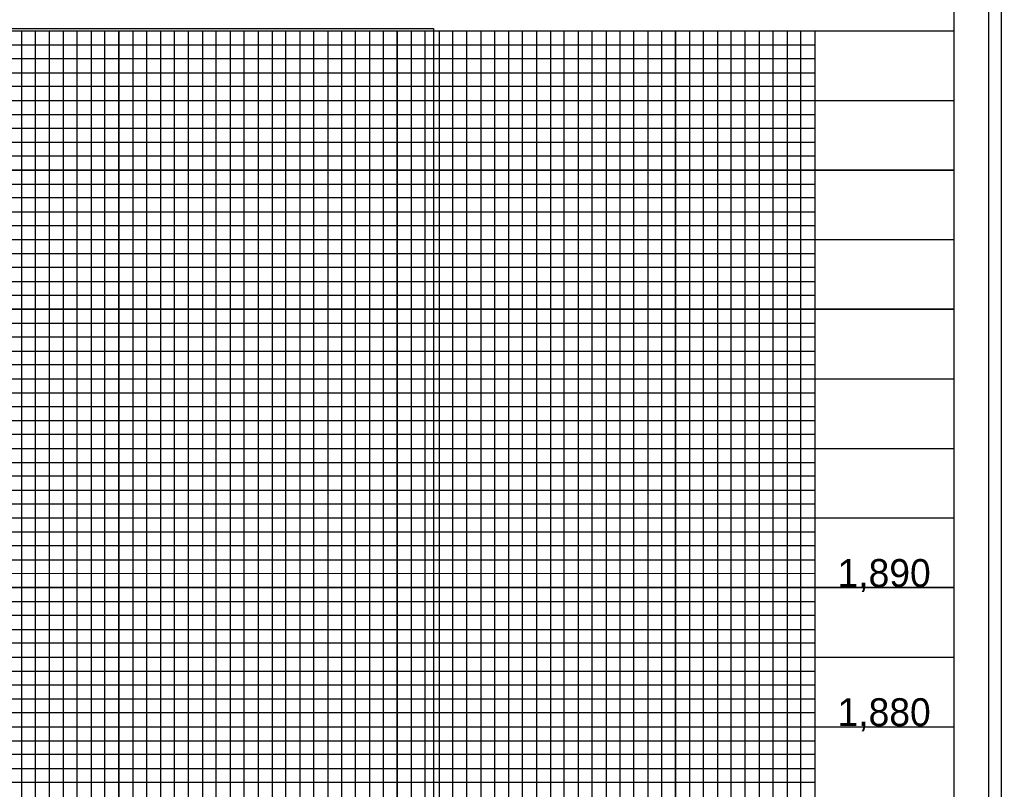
# Model space of a CAD drawing. Extents: x 557032 to 558716, y 525869 to 526969.
# Drawn here: x 558363.8 to 558716.5, y 526146.7 to 526423.3 of the extents above; entities that cross this region are included whole.
import ezdxf

# ---------------------------------------------------------------- set-up
doc = ezdxf.new("R2010")
doc.units = 0
for name, color, linetype in [('Exist Vertical Profile Vertical Axis Label', 7, 'Continuous'), ('Scratch_Level_5', 7, 'Continuous'), ('Sheet DOT Grid CELL', 7, 'Continuous'), ('Sheet Layout Profile Border Port 2', 7, 'Continuous'), ('Sheet Plot Border Inside CELL', 7, 'Continuous'), ('Sheet Plot Border Outside CELL', 7, 'Continuous'), ('Sheet Profile CELL', 7, 'Continuous'), ('Sheet Profile Grid Major CELL', 7, 'Continuous'), ('Sheet Profile Grid Middle CELL', 7, 'Continuous'), ('Sheet Profile Grid Minor CELL', 7, 'Continuous')]:
    doc.layers.add(name, color=color, linetype=linetype)

msp = doc.modelspace()

# ---------------------------------------------------------------- linework, layer by layer
at = {"layer": 'Scratch_Level_5'}
msp.add_lwpolyline([(557997.44, 526420.09), (558512.44, 526420.09), (558512.49, 525920.09), (557997.49, 525920.09)], close=True, dxfattribs=at)
at = {"layer": 'Sheet DOT Grid CELL'}
for p, q in [((557199.45, 526419.22), (558699.34, 526419.22)), ((558399.45, 526419.22), (558399.45, 525919.22)), ((558449.45, 526419.22), (558449.45, 525919.22)), ((558499.45, 526419.22), (558499.45, 525919.22)), ((558549.45, 526419.22), (558549.45, 525919.22)), ((558599.45, 526419.22), (558599.45, 525919.22)), ((558649.45, 526419.22), (558649.45, 525919.22)), ((557199.45, 526369.22), (558699.34, 526369.22)), ((557199.45, 526319.22), (558699.34, 526319.22)), ((557199.45, 526269.22), (558699.34, 526269.22)), ((557199.45, 526219.22), (558699.34, 526219.22)), ((557199.45, 526169.22), (558699.34, 526169.22))]:
    msp.add_line(p, q, dxfattribs=at)
at = {"layer": 'Sheet Layout Profile Border Port 2'}
msp.add_lwpolyline([(557249.45, 526419.22), (558649.45, 526419.22), (558649.45, 525919.22), (557249.45, 525919.22)], close=True, dxfattribs=at)
at = {"layer": 'Sheet Plot Border Inside CELL'}
msp.add_lwpolyline([(557045.45, 525891.67), (558711.95, 525891.67), (558711.95, 526946.77), (557045.45, 526946.77)], close=True, dxfattribs=at)
at = {"layer": 'Sheet Plot Border Outside CELL'}
msp.add_lwpolyline([(557032.45, 525869.22), (558716.45, 525869.22), (558716.45, 526969.22), (557032.45, 526969.22)], close=True, dxfattribs=at)
at = {"layer": 'Sheet Profile CELL'}
msp.add_line((557199.45, 526419.22), (558699.45, 526419.22), dxfattribs=at)
msp.add_lwpolyline([(558699.45, 526944.22), (557199.45, 526944.22), (557199.45, 525894.22), (558699.45, 525894.22)], close=True, dxfattribs=at)
at = {"layer": 'Sheet Profile Grid Major CELL'}
for p, q in [((558399.45, 526419.22), (558449.45, 526419.22)), ((558499.45, 526419.22), (558549.45, 526419.22)), ((558599.45, 526419.22), (558649.45, 526419.22))]:
    msp.add_line(p, q, dxfattribs=at)
for points in [[(558349.45, 525919.22), (558399.45, 525919.22), (558399.45, 526419.22), (558449.45, 526419.22), (558449.45, 525919.22), (558499.45, 525919.22), (558499.45, 526419.22), (558549.45, 526419.22), (558549.45, 526047.76)], [(558599.45, 526047.76), (558599.45, 526419.22), (558649.45, 526419.22), (558649.45, 525919.22)], [(558699.45, 526369.22), (557199.45, 526369.22)], [(558699.45, 526319.22), (557199.45, 526319.22), (557199.45, 526269.22), (558699.45, 526269.22)], [(558699.45, 526219.22), (557199.45, 526219.22), (557199.45, 526169.22), (558699.45, 526169.22)]]:
    msp.add_lwpolyline(points, dxfattribs=at)
at = {"layer": 'Sheet Profile Grid Middle CELL'}
for points in [[(558324.45, 526419.22), (558374.45, 526419.22), (558374.45, 525919.22), (558424.45, 525919.22), (558424.45, 526419.22), (558474.45, 526419.22), (558474.45, 525919.22), (558524.45, 525919.22), (558524.45, 526419.22), (558574.45, 526419.22), (558574.45, 526047.76)], [(558624.45, 526047.76), (558624.45, 526419.22)], [(557199.45, 526394.22), (558699.45, 526394.22)], [(558699.45, 526344.22), (557199.45, 526344.22), (557199.45, 526294.22), (558699.45, 526294.22)], [(558699.45, 526244.22), (557199.45, 526244.22), (557199.45, 526194.22), (558699.45, 526194.22)]]:
    msp.add_lwpolyline(points, dxfattribs=at)
at = {"layer": 'Sheet Profile Grid Minor CELL'}
for p, q in [((557249.45, 526414.22), (558649.45, 526414.22)), ((558649.45, 526409.22), (557249.45, 526409.22)), ((557249.45, 526404.22), (558649.45, 526404.22)), ((558649.45, 526399.22), (557249.45, 526399.22)), ((557249.45, 526389.22), (558649.45, 526389.22)), ((558649.45, 526384.22), (557249.45, 526384.22)), ((557249.45, 526379.22), (558649.45, 526379.22)), ((558649.45, 526374.22), (557249.45, 526374.22)), ((557249.45, 526364.22), (558649.45, 526364.22)), ((558649.45, 526359.22), (557249.45, 526359.22)), ((557249.45, 526354.22), (558649.45, 526354.22)), ((558649.45, 526349.22), (557249.45, 526349.22)), ((557249.45, 526339.22), (558649.45, 526339.22)), ((558649.45, 526334.22), (557249.45, 526334.22)), ((557249.45, 526329.22), (558649.45, 526329.22)), ((558649.45, 526324.22), (557249.45, 526324.22)), ((557249.45, 526314.22), (558649.45, 526314.22)), ((558649.45, 526309.22), (557249.45, 526309.22)), ((557249.45, 526304.22), (558649.45, 526304.22)), ((558649.45, 526299.22), (557249.45, 526299.22)), ((557249.45, 526289.22), (558649.45, 526289.22)), ((558649.45, 526284.22), (557249.45, 526284.22)), ((557249.45, 526279.22), (558649.45, 526279.22)), ((558649.45, 526274.22), (557249.45, 526274.22)), ((557249.45, 526264.22), (558649.45, 526264.22)), ((558649.45, 526259.22), (557249.45, 526259.22)), ((557249.45, 526254.22), (558649.45, 526254.22)), ((558649.45, 526249.22), (557249.45, 526249.22)), ((557249.45, 526239.22), (558649.45, 526239.22)), ((558649.45, 526234.22), (557249.45, 526234.22)), ((557249.45, 526229.22), (558649.45, 526229.22)), ((558649.45, 526224.22), (557249.45, 526224.37)), ((557249.45, 526214.22), (558649.45, 526214.22)), ((558649.45, 526209.22), (557249.45, 526209.22)), ((557249.45, 526204.22), (558649.45, 526204.22)), ((558649.45, 526199.22), (557249.45, 526199.22)), ((557249.45, 526189.22), (558649.45, 526189.22)), ((558649.45, 526184.22), (557249.45, 526184.22)), ((557249.45, 526179.22), (558649.45, 526179.22)), ((558649.45, 526174.22), (557249.45, 526174.22)), ((557249.45, 526164.22), (558649.45, 526164.22)), ((558649.45, 526159.22), (557249.45, 526159.22)), ((557249.45, 526154.22), (558649.45, 526154.22)), ((558649.45, 526149.22), (557249.45, 526149.22))]:
    msp.add_line(p, q, dxfattribs=at)
for points in [[(558359.45, 526419.22), (558364.45, 526419.22), (558364.45, 525919.22), (558369.45, 525919.22), (558369.45, 526419.22), (558379.45, 526419.22), (558379.45, 525919.22), (558384.45, 525919.22), (558384.45, 526419.22), (558389.45, 526419.22), (558389.45, 525919.22)], [(558394.45, 525919.22), (558394.45, 526419.22), (558404.45, 526419.22), (558404.45, 525919.22)], [(558409.45, 525919.22), (558409.45, 526419.22), (558414.45, 526419.22), (558414.45, 525919.22)], [(558419.45, 525919.22), (558419.45, 526419.22), (558429.45, 526419.22), (558429.45, 525919.22)], [(558434.45, 525919.22), (558434.45, 526419.22), (558439.45, 526419.22), (558439.45, 525919.22)], [(558444.45, 525919.22), (558444.45, 526419.22), (558454.45, 526419.22), (558454.45, 525919.22)], [(558459.45, 525919.22), (558459.45, 526419.22), (558464.45, 526419.22), (558464.45, 525919.22)], [(558469.45, 525919.22), (558469.45, 526419.22), (558479.45, 526419.22), (558479.45, 525919.22)], [(558484.45, 525919.22), (558484.45, 526419.22), (558489.45, 526419.22), (558489.45, 525919.22)], [(558494.45, 525919.22), (558494.45, 526419.22), (558504.45, 526419.22), (558504.45, 525919.22)], [(558509.45, 525919.22), (558509.45, 526419.22), (558514.45, 526419.22), (558514.45, 525919.22)], [(558519.45, 525919.22), (558519.45, 526419.22), (558529.45, 526419.22), (558529.45, 525919.22)], [(558534.45, 525919.22), (558534.45, 526419.22), (558539.45, 526419.22), (558539.45, 525919.22)], [(558544.45, 525919.22), (558544.45, 526419.22), (558554.45, 526419.22), (558554.45, 526047.76)], [(558559.45, 526047.76), (558559.45, 526419.22), (558564.45, 526419.22), (558564.45, 526047.76)], [(558569.45, 526047.76), (558569.45, 526419.22), (558579.45, 526419.22), (558579.45, 526047.76)], [(558584.45, 526047.76), (558584.45, 526419.22), (558589.45, 526419.22), (558589.45, 526047.76)], [(558594.45, 526047.76), (558594.45, 526419.22), (558604.45, 526419.22), (558604.45, 526047.76)], [(558609.45, 526047.76), (558609.45, 526419.22), (558614.45, 526419.22), (558614.45, 526047.76)], [(558619.45, 526047.76), (558619.45, 526419.22), (558629.45, 526419.22), (558629.45, 526047.76)], [(558629.45, 526021.97), (558629.45, 525919.22), (558634.45, 525919.22), (558634.45, 526419.22), (558639.45, 526419.22), (558639.45, 525919.22), (558644.45, 525919.22), (558644.45, 526419.22), (558649.45, 526419.22)]]:
    msp.add_lwpolyline(points, dxfattribs=at)

# ---------------------------------------------------------------- texts
at = {"layer": 'Exist Vertical Profile Vertical Axis Label'}
for s, p in [('1,890', (558657.61, 526219.47)), ('1,890', (558657.61, 526219.47)), ('1,880', (558657.61, 526169.47)), ('1,880', (558657.61, 526169.47))]:
    msp.add_text(s, height=10, dxfattribs=at).set_placement(p)

doc.saveas('drawing.dxf')
